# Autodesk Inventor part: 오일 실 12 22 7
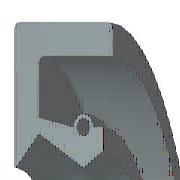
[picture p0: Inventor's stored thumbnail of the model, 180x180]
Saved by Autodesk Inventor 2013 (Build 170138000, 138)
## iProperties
Created: 2012-02
Part Number: 오일 실 12 22 7
Material: 고무
Description: 오일-실
Document SubType Name: Modeling
Standard: KS B 2804
Designer: mduedu
Standards Organization: KS
Language: ko-KR
Size Designation: D - 12 22 7
Categories: <MemberInstance><Categories><Category DisplayName="샤프트 부품" InternalName="7f7aeb1f-a693-4053-b835-cee3144e0d98" Mnemonic="SHFT"><Category DisplayName="실링" Intern
Density: 0.93 g/cm^3
Mass: 1.25383 g
Surface Area: 18.4996 cm^2
Volume: 1.3482 cm^3
IsCustomPart: 1
Author: mduedu
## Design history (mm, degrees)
revolve "본체" stored, may be unused: angle "d17" = 90 deg
revolve "스프링1" stored, may be unused: angle "d18" = 90 deg
body "Solid1"
sketch "스케치1"
  geometry: L1 (0, 11)-(7, 11); L2 (7, 9.25)-(1.75, 9.25); L3 (1.75, 7.75)-(4.9, 6); L4 (4.9, 6)-(0, 6); L5 (0, 0)-(9.586, 0) reference; L6 (4.9, 6)-(6.3, 6.875); L7 (0, 18)-(0, -3) reference; L8 (-1.941, 0)-(11.507, 0) reference; L9 (4.2, 8.1)-(1.75, 8.59); L10 (1.75, 8.59)-(1.75, 9.25); L11 (0, 11)-(0, 6.088); L12 (4.9, 6)-(0, 6); L13 (1.75, 7.75)-(0.152, 6.028); L14 (7, 11)-(7, 9.25); L15 (5.6, 8.1)-(6.3, 8.1); L16 (6.3, 8.1)-(6.3, 6.875); C1 r 0.455 at (4.9, 8.1); A1 r 0.7 centre (4.9, 8.1) between (5.6, 8.1) and (4.2, 8.1); A2 r 0.088 centre (0.088, 6.088) between (0, 6.088) and (0.152, 6.028); 1 further point
  constraints: 28 end point, 5 horizontal alignment, 5 point on line, 4 point on circle, 4 vertical alignment, 3 centre point, 3 tangent, 2 collinear, 2 horizontal, 2 perpendicular, 1 coincident, 1 parallel
  dimensions: "d0" = 22 diameter of L1 L5 (= SD2); "d1" = 1.75 distance of L1.end L2.start (= SD); "d2" = 0.91 diameter of C1 (= SPDI); "d3" = 1.4 diameter of A1 (= SPDA); "d4" = 12 diameter of L3.end L5 (= NND); "d5" = 15.5 diameter of L3.start L5 (= TKDM); "d7" = 17.18 diameter of L9.end L5 (= TKDM + 0.24 x SWDT); "d8" = 1.75 distance between parallel lines of L11 L10 (= SD); "d9" = 4.9 distance from line of L11 C1.centre (= SPDST); "d10" = 16.2 diameter of C1.centre L5 (= HLDM); "d11" = 0.0875 radius of A2 (= 0.25 x LAB); "d12" = 6.3 distance between parallel lines of L11 L16 (= SDI); "d13" = 13.75 diameter of L6.end L5 (= ABDM); "d14" = 7 distance from line of L11 L1.end (= SWDT)
fillet "모깎기1" dims "d6" = 0.3 (= RR)
other parameters: "SD2" = 22 [user parameter; used in 1 equation term], "SWDT" = 7 [user parameter; used in 2 equation terms], "RR" = 0.3 [user parameter; used in 1 equation term], "SD" = 1.75 [user parameter; used in 2 equation terms], "NND" = 12 [user parameter; used in 1 equation term], "SPDA" = 1.4 [user parameter; used in 1 equation term], "SPDI" = 0.91 [user parameter; used in 1 equation term], "TKDM" = 15.5 [user parameter; used in 2 equation terms], "HLDM" = 16.2 [user parameter; used in 1 equation term], "ABDM" = 13.75 [user parameter; used in 1 equation term], "SDI" = 6.3 [user parameter; used in 1 equation term], "SPDST" = 4.9 [user parameter; used in 1 equation term], "LAB" = 0.35 [user parameter; used in 1 equation term], "d15" = 0, "d16" = 0, "d19" = 0
